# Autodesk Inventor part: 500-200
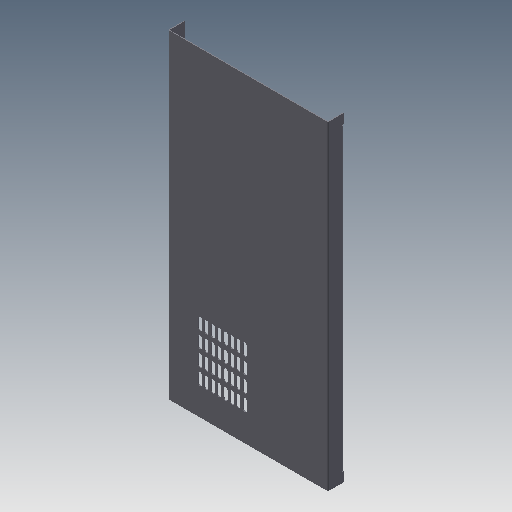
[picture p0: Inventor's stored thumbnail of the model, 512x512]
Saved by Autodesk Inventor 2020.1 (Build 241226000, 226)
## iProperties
Created: 2010-10
Part Number: 500-200
Material: St1203
Document SubType Name: Konstrukcje blachowe
Designer: F.Stasiak
Density: 7.85 g/cm^3
Sheet Metal Rule: Blacha stalowa 2.5 mm/Okrągły
Description: =Ściana lewa <WYSOKOŚĆ> x <SZEROKOŚĆ> perforowana
Appearance: Metal-Stal
Company: Fabian Stasiak CAD Consulting
Manager: www.cadconsulting.pl
SZEROKOŚĆ: 500
WYSOKOŚĆ: 1000
Author: F.Stasiak
Subject: Zbiór ćwiczeń. Autodesk Inventor 2020. Kurs podstawowy
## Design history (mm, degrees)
node "Powierzchnia1"
  sketch "Szkic1"
    geometry: L1 (-250, 1000)-(250, 1000); L2 (250, 1000)-(250, 0); L3 (250, 0)-(-250, 0); L4 (-250, 0)-(-250, 1000); 2 further points
    constraints: 8 end point, 2 parallel, 1 coincident, 1 horizontal, 1 midpoint, 1 perpendicular
    dimensions: "d0" = 500 distance of L2.end L3.end; "d1" = 1000 distance of L1.end L2.end
node "Kołnierz1"
node "Kołnierz2"
feature "Zawinięcie obrzeża1" dims "d25" = 2.5 (= SzerokośćGięciaPodcięcia), "d26" = 1.25 (= GłębokośćGięciaPodcięcia), "d27" = 5 (= MinimalnaPozostałość), "d28" = 2.5 (= PromieńGięcia), "d29" = 10 (= 4 x Grubość), "d30" = 1.25 (= 0.5 x Grubość), "d31" = 0.625 (= 0.5 x d30), "d54" = 2.5 (= Grubość), "OdstępPołączenia" = 0.01
sketch "Szkic5"
  geometry: L1 (245, 0)-(-245, 0) reference; L2 (-245, 1000)-(-245, 0) reference; L3 (-250, 0)-(-250, 1000) reference; 2 further points
  dimensions: "d32" = 104 distance from line of point (-150, 104) L1; "d34" = 100 distance from line of L3 point (-150, 104)
feature "iFeature18:1" sketch "Szkic5"
sketch "Szkic6"
  geometry: L1 (-45, 1000)-(-45, 0) reference; L2 (0, 0)-(-45, 0) reference; L3 (0, 0)-(0, 1000) reference; L4 (0, 1000)-(-45, 1000) reference; L5 (-22.5, 1000)-(-22.5, 0); 3 further points
  constraints: 2 end point, 2 midpoint, 2 point on line
  dimensions: "d45" = 130 distance from line of L4 point (-22.5, 870); "d46" = 150 distance of point (-22.5, 150) L5.end
hole "Hole1" sketch "Szkic6" at (-22.5, 870), (-22.5, 150) diameter "d47" = 12; stored, may be unused: countersink angle "d51" = 90 deg, drill point angle "d53" = 118 deg; dims "d48" = 6, "d49" = 4, "d50" = 2, "d52" = 2.5 (= Grubość)
node "Bryła1"
pattern_linear "Szyk prostokątny1" dims "d41" = 20, "d44" = 50
feature "Płyta1" dims "d54" = 2.5 (= Grubość)
sketch "Szkic2"
  geometry: L1 (0, -50)-(1000, -50); L2 (1000, -50)-(1000, 0); 1 other entity
  constraints: 4 end point, 4 other
feature "Płyta2" dims "d3" = 2.5 (= SzerokośćGięciaPodcięcia), "d4" = 1.25 (= GłębokośćGięciaPodcięcia), "d5" = 5 (= MinimalnaPozostałość), "d6" = 2.5 (= PromieńGięcia), "d7" = 50, "d8" = 90 deg, "d9" = 2.5 (= PromieńGięcia), "d10" = 10 (= RozmiarPodcięciaNarożnika), "d11" = 2.5 (= Wielk_odstępu), "d12" = 2.5 (= Rozmiar_promienia_Jacobiego), "d54" = 2.5 (= Grubość), "OdstępPołączenia" = 0.01
feature "Gięcie1" dims "d3" = 2.5 (= SzerokośćGięciaPodcięcia), "d4" = 1.25 (= GłębokośćGięciaPodcięcia), "d5" = 5 (= MinimalnaPozostałość), "d6" = 2.5 (= PromieńGięcia), "d7" = 50, "d8" = 90 deg, "d9" = 2.5 (= PromieńGięcia), "d54" = 2.5 (= Grubość), "OdstępPołączenia" = 0.01
feature "Narożnik1" dims "d7" = 50, "d8" = 90 deg, "d10" = 10 (= RozmiarPodcięciaNarożnika), "d11" = 2.5 (= Wielk_odstępu), "d12" = 2.5 (= Rozmiar_promienia_Jacobiego)
sketch "Szkic3"
  geometry: L1 (0, 968)-(0, 32); L2 (0, 32)-(20, 32); L3 (20, 32)-(20, 968); L4 (20, 968)-(0, 968)
  constraints: 8 end point
feature "Płyta3" dims "d13" = 2.5 (= SzerokośćGięciaPodcięcia), "d14" = 1.25 (= GłębokośćGięciaPodcięcia), "d15" = 5 (= MinimalnaPozostałość), "d16" = 2.5 (= PromieńGięcia), "d17" = 32, "d18" = 32, "d19" = 20, "d20" = 90 deg, "d21" = 2.5 (= PromieńGięcia), "d22" = 10 (= RozmiarPodcięciaNarożnika), "d23" = 2.5 (= Wielk_odstępu), "d24" = 2.5 (= Rozmiar_promienia_Jacobiego), "d54" = 2.5 (= Grubość), "OdstępPołączenia" = 0.01
feature "Gięcie2" dims "d13" = 2.5 (= SzerokośćGięciaPodcięcia), "d14" = 1.25 (= GłębokośćGięciaPodcięcia), "d15" = 5 (= MinimalnaPozostałość), "d16" = 2.5 (= PromieńGięcia), "d19" = 20, "d20" = 90 deg, "d21" = 2.5 (= PromieńGięcia), "d54" = 2.5 (= Grubość), "OdstępPołączenia" = 0.01
feature "Narożnik2" dims "d19" = 20, "d20" = 90 deg, "d22" = 10 (= RozmiarPodcięciaNarożnika), "d23" = 2.5 (= Wielk_odstępu), "d24" = 2.5 (= Rozmiar_promienia_Jacobiego)
node "Pętla rzutowana1"
sketch "Szkic4"
  geometry: L1 (0, -2.5)-(0, 0); L2 (0, 1.25)-(-6.875, 1.25); L3 (-6.875, 1.25)-(-6.875, 3.75); L4 (-6.875, 3.75)-(0, 3.75); A1 r 0.625 centre (0, 0.625) between (0, 0) and (0, 1.25); A2 r 3.125 centre (0, 0.625) between (0, -2.5) and (0, 3.75)
  constraints: 8 end point, 4 point on circle
other parameters: "Grubość" = 2.5 (derived), "WspółczynnikK" = 4.4, "PromieńGięcia" = 2.5 (= Grubość), "SzerokośćGięciaPodcięcia" = 2.5 (= Grubość), "GłębokośćGięciaPodcięcia" = 1.25 (= 0.5 x Grubość), "MinimalnaPozostałość" = 5 (= 2 x Grubość), "PromieńPrzejścia" = 2.5 (= PromieńGięcia), "Rozmiar_promienia_Jacobiego" = 2.5 (= PromieńGięcia), "Wielk_odstępu" = 2.5 (= Grubość), "d2" = 2.5 (= PromieńGięcia), "d38" = 90 deg
